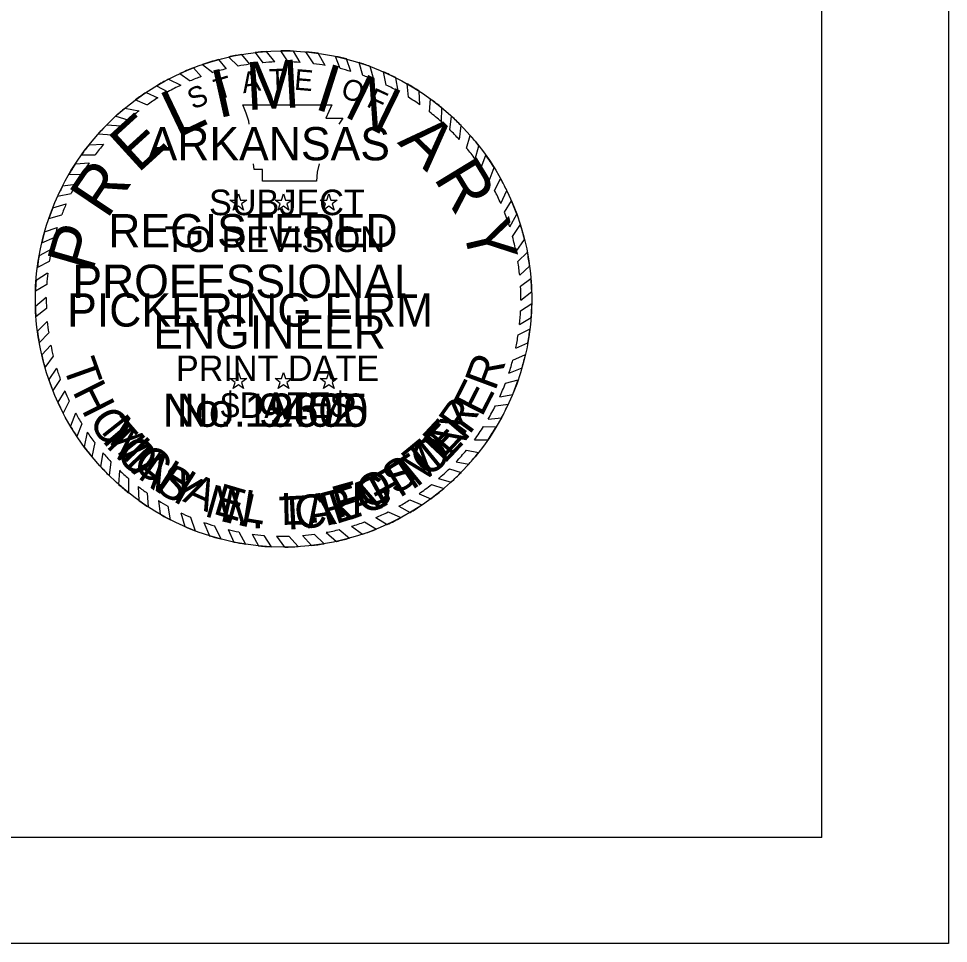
# Model space of a CAD drawing. Extents: x 1368042 to 1371376, y 380392 to 382637.
# Drawn here: x 1371026.4 to 1371375.6, y 380392 to 380739.5 of the extents above; entities that cross this region are included whole.
import ezdxf

# ---------------------------------------------------------------- set-up
doc = ezdxf.new("R2010")
doc.units = 0
for name, color, linetype in [('R_Border', 7, 'Continuous'), ('R_No Plot', 7, 'Continuous'), ('STAMP_PE_CRAFTON', 7, 'Continuous'), ('STAMP_PE_FOSTER', 7, 'Continuous'), ('STAMP_PE_SEAL-INFO', 7, 'Continuous'), ('STAMP_PE_TAEGTMEYER', 7, 'Continuous'), ('STAMP_PE_TXT', 7, 'Continuous'), ('STAMP_PRELIMINARY', 7, 'Continuous')]:
    doc.layers.add(name, color=color, linetype=linetype)

msp = doc.modelspace()

# ---------------------------------------------------------------- linework, layer by layer
at = {"layer": 'R_Border'}
for q in [(1371328.04, 382486.41), (1368166.24, 380431.81)]:
    msp.add_line((1371328.04, 380431.81), q, dxfattribs=at)
at = {"layer": 'R_No Plot'}
msp.add_line((1368042.23, 380392.03), (1371375.57, 380392.03), dxfattribs=at)
msp.add_lwpolyline([(1368042.17, 382525.36), (1371375.57, 382525.36), (1371375.57, 380391.98), (1368042.17, 380391.98)], close=True, dxfattribs=at)
at = {"layer": 'STAMP_PE_SEAL-INFO'}
for p, q in [((1371122.6, 380723.21), (1371119.48, 380727.14)), ((1371127.58, 380723.26), (1371124.79, 380727.36)), ((1371132.15, 380723.05), (1371129.57, 380727.29)), ((1371137.21, 380722.55), (1371134.29, 380726.98)), ((1371101.38, 380724.09), (1371104.26, 380720.61)), ((1371105.26, 380725.06), (1371108.82, 380721.62)), ((1371110.09, 380726.02), (1371113.08, 380722.35)), ((1371115.24, 380726.75), (1371118.05, 380722.93)), ((1371141.47, 380721.9), (1371138.9, 380726.45)), ((1371147.09, 380720.71), (1371145.35, 380725.31)), ((1371151.11, 380719.63), (1371149.52, 380724.32)), ((1371092, 380720.99), (1371094.94, 380717.73)), ((1371095.47, 380722.27), (1371099.28, 380719.21)), ((1371155.63, 380718.16), (1371154.21, 380722.95)), ((1371159.81, 380716.56), (1371158.37, 380721.52)), ((1371082.61, 380716.71), (1371087.24, 380714.46)), ((1371086.92, 380718.83), (1371090.81, 380716.08)), ((1371164.42, 380714.51), (1371163.4, 380719.48)), ((1371168.88, 380712.21), (1371168.01, 380717.3)), ((1371078.13, 380714.21), (1371082.45, 380711.98)), ((1371172.76, 380709.95), (1371172.36, 380714.95)), ((1371074.26, 380711.77), (1371078.68, 380709.75)), ((1371177.1, 380707.08), (1371176.79, 380712.23)), ((1371070.06, 380709.1), (1371074.61, 380707.05)), ((1371110.61, 380707.05), (1371144.05, 380707.05)), ((1371111.82, 380703.98), (1371110.61, 380707.05)), ((1371144.05, 380707.05), (1371141.8, 380702.13)), ((1371180.71, 380704.41), (1371181.05, 380709.29)), ((1371185.17, 380700.69), (1371185.37, 380705.92)), ((1371062.85, 380702.83), (1371067.44, 380701.44)), ((1371066.29, 380705.83), (1371071.58, 380704.82)), ((1371112.86, 380701), (1371111.82, 380703.98)), ((1371188.3, 380697.77), (1371188.99, 380702.75)), ((1371059.5, 380699.59), (1371064.94, 380699.18)), ((1371112.93, 380699.86), (1371112.86, 380701)), ((1371141.8, 380702.13), (1371148.13, 380702.13)), ((1371148.13, 380702.13), (1371146.68, 380699.86)), ((1371191.89, 380694.03), (1371192.56, 380699.29)), ((1371056.27, 380696.15), (1371061.48, 380695.77)), ((1371194.63, 380690.87), (1371195.99, 380695.58)), ((1371052.81, 380692.04), (1371058.3, 380692.26)), ((1371197.87, 380686.7), (1371199.22, 380691.69)), ((1371047.69, 380684.9), (1371052.85, 380685.24)), ((1371050.03, 380688.34), (1371055.08, 380688.29)), ((1371114.85, 380682.77), (1371114.58, 380684.94)), ((1371139.22, 380684.94), (1371138.44, 380681.84)), ((1371200.07, 380683.55), (1371201.84, 380688.18)), ((1371117.99, 380682.77), (1371114.85, 380682.77)), ((1371117.99, 380678.46), (1371117.99, 380682.77)), ((1371138.44, 380681.84), (1371138.29, 380678.46)), ((1371203.15, 380678.57), (1371204.97, 380683.49)), ((1371045.22, 380680.89), (1371050.12, 380681.09)), ((1371138.29, 380678.46), (1371117.99, 380678.46)), ((1371205.14, 380674.91), (1371207.41, 380679.35)), ((1371042.91, 380676.66), (1371047.9, 380677.31)), ((1371207.45, 380670.07), (1371209.71, 380674.92)), ((1371041.03, 380672.77), (1371046.06, 380673.81)), ((1371208.85, 380666.7), (1371211.49, 380671.03)), ((1371039.19, 380668.44), (1371044.24, 380669.91)), ((1371037.69, 380664.38), (1371042.54, 380665.74)), ((1371210.8, 380661.21), (1371213.51, 380665.95)), ((1371036.13, 380659.35), (1371040.9, 380661.04)), ((1371211.88, 380657.56), (1371214.82, 380662.08)), ((1371035.08, 380655.28), (1371039.78, 380657.2)), ((1371213.21, 380651.98), (1371216.4, 380656.44)), ((1371038.72, 380652.81), (1371034.07, 380650.32)), ((1371213.9, 380648.17), (1371217.44, 380651.7)), ((1371037.87, 380648.23), (1371033.41, 380646)), ((1371037.28, 380643.87), (1371032.91, 380641.06)), ((1371214.56, 380643.08), (1371218.29, 380646.44)), ((1371036.91, 380639.62), (1371032.7, 380637.05)), ((1371214.89, 380638.9), (1371218.79, 380641.82)), ((1371215.01, 380633.72), (1371219.06, 380636.94)), ((1371036.75, 380634.69), (1371032.69, 380631.33)), ((1371036.81, 380630.62), (1371032.9, 380627.37)), ((1371214.9, 380629.67), (1371219.09, 380632.44)), ((1371037.15, 380625.66), (1371033.43, 380622.1)), ((1371214.5, 380624.61), (1371218.85, 380627.17)), ((1371214, 380620.72), (1371218.43, 380622.92)), ((1371037.66, 380621.37), (1371034.12, 380617.64)), ((1371038.45, 380616.78), (1371035.06, 380613.11)), ((1371213.09, 380615.72), (1371217.64, 380617.68)), ((1371039.39, 380612.59), (1371036.26, 380608.44)), ((1371212.01, 380611.21), (1371216.73, 380613.22)), ((1371040.62, 380608.12), (1371037.68, 380603.94)), ((1371210.54, 380606.26), (1371215.45, 380608.27)), ((1371042.03, 380603.89), (1371039.22, 380599.78)), ((1371209.2, 380602.46), (1371214.02, 380603.77)), ((1371043.69, 380599.63), (1371041.08, 380595.41)), ((1371207.06, 380597.32), (1371211.94, 380598.29)), ((1371045.41, 380595.79), (1371043.14, 380591.19)), ((1371205.45, 380593.96), (1371210.33, 380594.64)), ((1371047.76, 380591.21), (1371045.85, 380586.31)), ((1371050.12, 380587.18), (1371048.28, 380582.47)), ((1371202.72, 380588.97), (1371207.73, 380589.52)), ((1371052.14, 380584.06), (1371051.05, 380578.54)), ((1371201.01, 380586.17), (1371205.78, 380586.1)), ((1371197.61, 380581.22), (1371202.66, 380581.25)), ((1371054.95, 380580.15), (1371053.93, 380574.85)), ((1371194.53, 380577.29), (1371199.15, 380576.49)), ((1371057.99, 380576.38), (1371057.12, 380571.18)), ((1371061.02, 380573), (1371060.4, 380567.78)), ((1371064.24, 380569.75), (1371063.94, 380564.46)), ((1371188.15, 380570.36), (1371192.56, 380568.98)), ((1371190.7, 380572.95), (1371195.47, 380572.1)), ((1371067.68, 380566.62), (1371067.65, 380561.33)), ((1371184.09, 380566.64), (1371188.8, 380565.35)), ((1371071.28, 380563.68), (1371071.47, 380558.43)), ((1371181.38, 380564.39), (1371186.06, 380562.94)), ((1371074.67, 380561.18), (1371075.03, 380556)), ((1371176.78, 380560.96), (1371181.17, 380559.07)), ((1371078.94, 380558.36), (1371079.54, 380553.24)), ((1371082.44, 380556.3), (1371083.35, 380551.17)), ((1371169.2, 380556.24), (1371173.37, 380553.91)), ((1371173.34, 380558.69), (1371177.84, 380556.73)), ((1371087.25, 380553.81), (1371088.82, 380548.59)), ((1371165.12, 380554.1), (1371169.96, 380551.99)), ((1371090.98, 380552.12), (1371092.71, 380547.01)), ((1371095.9, 380550.19), (1371098, 380545.18)), ((1371100, 380548.84), (1371102.26, 380543.95)), ((1371151.41, 380548.74), (1371155.57, 380545.76)), ((1371156.33, 380550.37), (1371160.76, 380547.68)), ((1371160.53, 380552.01), (1371164.76, 380549.4)), ((1371105.08, 380547.46), (1371107.2, 380542.8)), ((1371109.05, 380546.6), (1371111.52, 380542.02)), ((1371114.06, 380545.79), (1371116.45, 380541.39)), ((1371118.42, 380545.31), (1371121.16, 380541.03)), ((1371133.05, 380545.29), (1371136.31, 380541.5)), ((1371137.43, 380545.75), (1371141.16, 380542.17)), ((1371141.89, 380546.45), (1371145.77, 380543.06)), ((1371146.81, 380547.49), (1371150.59, 380544.24)), ((1371123.27, 380545.04), (1371126.29, 380540.91)), ((1371127.87, 380545.02), (1371131.3, 380541.07))]:
    msp.add_line(p, q, dxfattribs=at)
for radius, start, end in [(93.23, 93.9381, 96.5517), (93.23, 87.7298, 90.6707), (93.23, 81.9732, 84.8236), (93.23, 105.2339, 109.0352), (93.23, 99.7525, 102.7765), (93.23, 75.3125, 77.9426), (93.23, 111.3124, 114.7026), (89.13, 104.0352, 107.3615), (89.13, 98.258, 101.0329), (89.13, 92.1102, 95.0367), (89.13, 85.9628, 88.9097), (89.13, 79.9264, 82.696), (89.13, 73.5575, 76.2314), (93.23, 69.6061, 72.3058), (93.23, 117.6544, 120.8099), (89.13, 110.3086, 113.1659), (89.13, 67.6248, 70.504), (93.23, 63.1329, 66.2704), (89.13, 115.6869, 119.1583), (89.13, 61.1558, 64.3784), (93.23, 56.9003, 60.0942), (93.23, 123.6199, 126.5906), (89.13, 121.9746, 125.11), (89.13, 54.9238, 58.2702), (93.23, 50.3492, 53.7159), (93.23, 129.7326, 132.5376), (89.13, 127.5297, 130.9683), (89.13, 48.3016, 52.0395), (93.23, 44.3405, 47.3929), (93.23, 135.4021, 138.3031), (89.13, 133.1331, 136.2562), (89.13, 42.2212, 45.5512), (93.23, 38.1247, 41.2316), (93.23, 141.6056, 144.4486), (89.13, 139.301, 142.5873), (89.13, 36.135, 39.5311), (89.13, 145.0197, 148.2104), (93.23, 31.9614, 35.4294), (93.23, 147.0072, 149.899), (89.13, 29.9032, 33.6645), (93.23, 25.9391, 29.0125), (93.23, 152.864, 155.5189), (89.13, 151.0315, 153.573), (89.13, 23.7732, 27.2211), (93.23, 19.9538, 23.3141), (93.23, 158.4077, 161.0701), (89.13, 156.3402, 159.2319), (89.13, 17.6802, 21.4251), (89.13, 162.4331, 165.0013), (93.23, 13.8421, 17.4447), (93.23, 164.3068, 166.894), (89.13, 11.5444, 15.2364), (93.23, 170.0003, 172.6878), (89.13, 167.9048, 170.9039), (93.23, 7.5852, 10.8621), (89.13, 5.7599, 9.0606), (89.13, 173.73, 176.4734), (93.23, 175.7409, 178.2066), (93.23, 1.7215, 4.7268), (89.13, 359.7329, 3.0639), (89.13, 179.6454, 182.2633), (93.23, 181.7251, 184.1626), (89.13, 353.8632, 357.1274), (93.23, 355.7156, 358.9569), (89.13, 185.4539, 188.234), (93.23, 187.4204, 190.1927), (93.23, 349.8305, 353.0885), (89.13, 348.0778, 351.3435), (89.13, 191.2274, 193.9858), (93.23, 193.0369, 195.9973), (93.23, 343.8925, 347.035), (89.13, 196.9675, 199.8353), (89.13, 341.777, 345.0925), (93.23, 198.8967, 201.6281), (89.13, 335.6038, 339.1858), (93.23, 337.3837, 340.9933), (89.13, 202.7761, 205.4791), (93.23, 204.5479, 207.4328), (93.23, 331.4037, 334.9332), (89.13, 208.7883, 211.7934), (89.13, 329.5549, 333.2076), (93.23, 210.8636, 213.6571), (89.13, 214.1838, 217.2747), (89.13, 323.5851, 327.4407), (93.23, 325.4405, 328.9872), (93.23, 216.6115, 219.491), (89.13, 316.6531, 320.3711), (89.13, 220.3909, 223.3056), (93.23, 318.2846, 321.8043), (93.23, 222.48, 225.3801), (89.13, 226.2494, 229.2407), (89.13, 310.7744, 314.3161), (93.23, 312.4518, 315.6633), (93.23, 228.3665, 231.348), (89.13, 232.229, 234.9336), (89.13, 304.823, 308.5143), (93.23, 306.3721, 310.208), (93.23, 234.295, 236.9452), (89.13, 238.2223, 240.8353), (89.13, 299.0768, 302.1724), (93.23, 300.621, 303.8703), (93.23, 240.1977, 242.8613), (89.13, 244.3204, 246.9486), (89.13, 292.8745, 296.1185), (89.13, 250.3491, 253.1216), (89.13, 286.6423, 289.9783), (93.23, 294.6481, 298.2166), (93.23, 246.576, 249.1558), (89.13, 256.505, 259.1192), (89.13, 262.3783, 265.2012), (89.13, 274.6157, 277.4486), (89.13, 280.3459, 283.5814), (93.23, 288.5709, 291.9733), (93.23, 252.5967, 255.3252), (93.23, 258.4433, 261.1398), (89.13, 268.3215, 271.277), (93.23, 276.4239, 279.4357), (93.23, 282.3199, 285.3702), (93.23, 264.1978, 267.1009), (93.23, 270.2548, 273.3361)]:
    msp.add_arc((1371125.88, 380634.14), radius, start, end, dxfattribs=at)
at = {"layer": 'STAMP_PE_TXT'}
for p, q in [((1371107.67, 380669.85), (1371105.69, 380671.29)), ((1371105.69, 380671.29), (1371108.14, 380671.29)), ((1371108.14, 380671.29), (1371108.9, 380673.62)), ((1371108.9, 380673.62), (1371109.66, 380671.29)), ((1371109.66, 380671.29), (1371112.11, 380671.29)), ((1371112.11, 380671.29), (1371110.13, 380669.85)), ((1371124.65, 380669.85), (1371122.67, 380671.29)), ((1371122.67, 380671.29), (1371125.12, 380671.29)), ((1371125.12, 380671.29), (1371125.88, 380673.62)), ((1371125.88, 380673.62), (1371126.64, 380671.29)), ((1371126.64, 380671.29), (1371129.09, 380671.29)), ((1371129.09, 380671.29), (1371127.11, 380669.85)), ((1371141.63, 380669.85), (1371139.65, 380671.29)), ((1371139.65, 380671.29), (1371142.1, 380671.29)), ((1371142.1, 380671.29), (1371142.86, 380673.62)), ((1371142.86, 380673.62), (1371143.62, 380671.29)), ((1371143.62, 380671.29), (1371146.07, 380671.29)), ((1371146.07, 380671.29), (1371144.09, 380669.85)), ((1371106.92, 380667.52), (1371107.67, 380669.85)), ((1371108.9, 380668.96), (1371106.92, 380667.52)), ((1371110.88, 380667.52), (1371108.9, 380668.96)), ((1371110.13, 380669.85), (1371110.88, 380667.52)), ((1371123.9, 380667.52), (1371124.65, 380669.85)), ((1371125.88, 380668.96), (1371123.9, 380667.52)), ((1371127.86, 380667.52), (1371125.88, 380668.96)), ((1371127.11, 380669.85), (1371127.86, 380667.52)), ((1371140.88, 380667.52), (1371141.63, 380669.85)), ((1371142.86, 380668.96), (1371140.88, 380667.52)), ((1371144.84, 380667.52), (1371142.86, 380668.96)), ((1371144.09, 380669.85), (1371144.84, 380667.52)), ((1371108.14, 380604.22), (1371108.9, 380606.55)), ((1371108.9, 380606.55), (1371109.66, 380604.22)), ((1371125.12, 380604.22), (1371125.88, 380606.55)), ((1371125.88, 380606.55), (1371126.64, 380604.22)), ((1371142.1, 380604.22), (1371142.86, 380606.55)), ((1371142.86, 380606.55), (1371143.62, 380604.22)), ((1371107.67, 380602.78), (1371105.69, 380604.22)), ((1371105.69, 380604.22), (1371108.14, 380604.22)), ((1371106.92, 380600.45), (1371107.67, 380602.78)), ((1371108.9, 380601.89), (1371106.92, 380600.45)), ((1371110.88, 380600.45), (1371108.9, 380601.89)), ((1371109.66, 380604.22), (1371112.11, 380604.22)), ((1371112.11, 380604.22), (1371110.13, 380602.78)), ((1371110.13, 380602.78), (1371110.88, 380600.45)), ((1371124.65, 380602.78), (1371122.67, 380604.22)), ((1371122.67, 380604.22), (1371125.12, 380604.22)), ((1371123.9, 380600.45), (1371124.65, 380602.78)), ((1371125.88, 380601.89), (1371123.9, 380600.45)), ((1371127.86, 380600.45), (1371125.88, 380601.89)), ((1371126.64, 380604.22), (1371129.09, 380604.22)), ((1371129.09, 380604.22), (1371127.11, 380602.78)), ((1371127.11, 380602.78), (1371127.86, 380600.45)), ((1371141.63, 380602.78), (1371139.65, 380604.22)), ((1371139.65, 380604.22), (1371142.1, 380604.22)), ((1371140.88, 380600.45), (1371141.63, 380602.78)), ((1371142.86, 380601.89), (1371140.88, 380600.45)), ((1371144.84, 380600.45), (1371142.86, 380601.89)), ((1371143.62, 380604.22), (1371146.07, 380604.22)), ((1371146.07, 380604.22), (1371144.09, 380602.78)), ((1371144.09, 380602.78), (1371144.84, 380600.45))]:
    msp.add_line(p, q, dxfattribs=at)
at = {"layer": 'STAMP_PRELIMINARY'}
msp.add_circle((1371125.88, 380634.14), 93.23, dxfattribs=at)
msp.add_circle((1371125.88, 380634.14), 93.23, dxfattribs=at)

# ---------------------------------------------------------------- texts
at = {"layer": 'STAMP_PE_CRAFTON'}
msp.add_text('No. 12370', height=12.5, dxfattribs=at).set_placement((1371080.5, 380586.11))
for s, rotation, p in [('T', 310.7442, (1371055.54, 380583.11)), ('N', 49.2411, (1371188.7, 380574.36)), ('O', 317.6422, (1371062.21, 380575)), ('O', 41.8391, (1371180.23, 380566.54)), ('N', 324.4537, (1371070.67, 380567.15)), ('T', 34.1136, (1371171.65, 380560.53)), ('Y', 331.1686, (1371081, 380559.99)), ('F', 28.7821, (1371162.49, 380555.43)), ('N', 347.4752, (1371101.54, 380550.83)), ('R', 14.8189, (1371141.56, 380548.7)), ('A', 20.5125, (1371152.69, 380551.7)), ('C', 6.0117, (1371130.59, 380547.55)), ('.', 356.8926, (1371113.84, 380548.06))]:
    msp.add_text(s, height=12.5, rotation=rotation, dxfattribs=at).set_placement(p)
at = {"layer": 'STAMP_PE_FOSTER'}
msp.add_text('No. 9402', height=12.5, dxfattribs=at).set_placement((1371085.74, 380586.11))
for s, rotation, p in [('R', 54.5031, (1371193.12, 380582.25)), ('M', 308.339, (1371057.04, 380584.36)), ('E', 46.9613, (1371185.89, 380574.04)), ('I', 314.1842, (1371065.02, 380574.98)), ('T', 39.4194, (1371177.3, 380566.54)), ('C', 319.8733, (1371068.56, 380571.45)), ('H', 327.7235, (1371077.85, 380564.09)), ('S', 31.7234, (1371167.79, 380560.26)), ('A', 335.7276, (1371087.66, 380558.27)), ('O', 23.719, (1371156.67, 380554.96)), ('E', 343.5779, (1371099.03, 380553.56)), ('F', 15.8691, (1371146.23, 380551.68)), ('L', 350.8115, (1371109.62, 380550.79)), ('L', 1.2666, (1371125.01, 380549.22)), ('.', 6.8035, (1371135.48, 380549.81))]:
    msp.add_text(s, height=12, rotation=rotation, dxfattribs=at).set_placement(p)
at = {"layer": 'STAMP_PE_TAEGTMEYER'}
for s, rotation, p in [('T', 289.646, (1371042.82, 380609.24)), ('R', 69.57, (1371205.33, 380599.28)), ('H', 296.7339, (1371046.42, 380599.39)), ('E', 63.0984, (1371200.34, 380589.47)), ('Y', 53.9986, (1371193.65, 380580.06)), ('O', 303.7708, (1371052.35, 380588.31)), ('E', 46.8094, (1371186.26, 380571.91)), ('M', 314.2033, (1371058.9, 380578.8)), ('M', 39.3, (1371175.86, 380563.12)), ('A', 321.0594, (1371068.52, 380569.16)), ('T', 31.466, (1371166.88, 380557.69)), ('S', 327.8239, (1371076.78, 380562.72)), ('G', 23.3052, (1371155.88, 380552.76)), ('N', 344.2727, (1371095.75, 380552.65)), ('E', 17.6836, (1371145.38, 380549.45)), ('T', 3.0061, (1371124.52, 380547.34)), ('A', 8.9826, (1371134.99, 380547.9)), ('.', 350.6464, (1371107.87, 380549.33))]:
    msp.add_text(s, height=12.5, rotation=rotation, dxfattribs=at).set_placement(p)
msp.add_text('No. 19605', height=12.5, dxfattribs=at).set_placement((1371080.5, 380586.11))
at = {"layer": 'STAMP_PE_TXT'}
for s, rotation, p in [('T', 1.8248, (1371120.58, 380712.72)), ('E', 355.2002, (1371129.69, 380712.81)), ('T', 16.311, (1371101.1, 380708.9)), ('A', 9.0679, (1371110.72, 380711.42)), ('O', 342.2506, (1371146.95, 380710.04)), ('S', 23.5541, (1371091.87, 380705.18)), ('F', 335.0075, (1371156.61, 380706.66))]:
    msp.add_text(s, height=7.81, rotation=rotation, dxfattribs=at).set_placement(p)
for s, p in [('ARKANSAS', (1371074.8, 380686.24)), ('REGISTERED', (1371060.05, 380653.55)), ('PROFESSIONAL', (1371046.56, 380634.53)), ('ENGINEER', (1371076.97, 380615.52))]:
    msp.add_text(s, height=12.5, dxfattribs=at).set_placement(p)
at = {"layer": 'STAMP_PRELIMINARY'}
for s, rotation, p in [('M', 3.1074, (1371112.24, 380705.1)), ('M', 3.1074, (1371112.24, 380705.09)), ('I', 12.5248, (1371101.25, 380702)), ('I', 12.5248, (1371101.26, 380702)), ('I', 342.3164, (1371136.91, 380705.77)), ('I', 342.3164, (1371136.91, 380705.77)), ('N', 333.9382, (1371147.99, 380703.03)), ('N', 333.9382, (1371147.99, 380703.03)), ('L', 25.513, (1371085.97, 380694.41)), ('L', 25.513, (1371085.97, 380694.41)), ('E', 42.3578, (1371071.14, 380681.1)), ('E', 42.3578, (1371071.14, 380681.1)), ('A', 315.6579, (1371168.33, 380692.77)), ('A', 315.6579, (1371168.33, 380692.77)), ('R', 56.2292, (1371059.58, 380663.78)), ('R', 56.2292, (1371059.59, 380663.78)), ('R', 301.3831, (1371182.01, 380679.63)), ('R', 301.3831, (1371182.01, 380679.63)), ('Y', 283.2593, (1371192.9, 380661.77)), ('Y', 283.2593, (1371192.9, 380661.77)), ('P', 73.913, (1371054.09, 380643.54)), ('P', 73.913, (1371054.09, 380643.54))]:
    msp.add_text(s, height=18, rotation=rotation, dxfattribs=at).set_placement(p)
for s, height, p in [('SUBJECT', 9.6, (1371097.88, 380665.63)), ('SUBJECT', 9.6, (1371097.88, 380665.63)), ('TO REVISION', 9.6, (1371081.23, 380651.78)), ('TO REVISION', 9.6, (1371081.23, 380651.78)), ('PICKERING FIRM', 12.5, (1371044.61, 380623.77)), ('PICKERING FIRM', 12.5, (1371044.61, 380623.77)), ('PRINT DATE', 9.6, (1371085.45, 380603.29)), ('PRINT DATE', 9.6, (1371085.45, 380603.29)), ('$DATE$', 9.6, (1371102.22, 380589.44)), ('$DATE$', 9.6, (1371102.22, 380589.44))]:
    msp.add_text(s, height=height, dxfattribs=at).set_placement(p)

doc.saveas('drawing.dxf')
